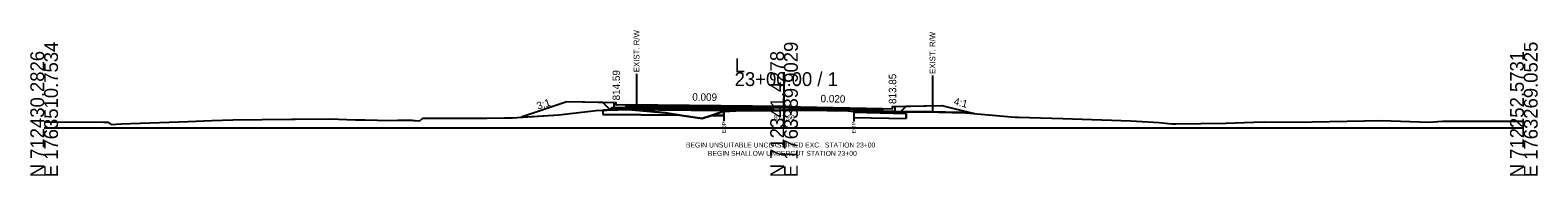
# Model space of a CAD drawing. Extents: x -26 to 5303, y -10 to 9578.
# Drawn here: x 997.2 to 1302.8, y 2990.3 to 3019.8 of the extents above; entities that cross this region are included whole.
import ezdxf

# ---------------------------------------------------------------- set-up
doc = ezdxf.new("R2010")
doc.units = 0
for name, color, linetype in [('Default', 7, 'Continuous'), ('Exist CMT Pavement', 7, 'Continuous'), ('Exist Cross Section Cell', 7, 'Continuous'), ('Exist XS Ground Line', 7, 'Continuous'), ('Old_Level_10', 7, 'Continuous'), ('Old_Level_3', 7, 'Continuous'), ('Old_Level_4', 7, 'Continuous'), ('Prop CMT Conc Surface', 7, 'Continuous'), ('Prop CMT Concrete Structures', 7, 'Continuous'), ('Prop CMT Pvmt Course 1', 7, 'Continuous'), ('Prop CMT Pvmt Course 1 CG', 7, 'Continuous'), ('Prop CMT Pvmt Course 2', 7, 'Continuous'), ('Prop CMT Pvmt Course 3', 7, 'Continuous'), ('Prop CMT Pvmt Surface', 7, 'Continuous'), ('Prop CMT Slope Grass', 7, 'Continuous'), ('Prop CMT Subgrade Earthwork', 7, 'Continuous'), ('Prop Shade Light', 7, 'Continuous'), ('Prop XS Earthwork Shape', 7, 'Continuous'), ('Prop XS Hydro Elevations', 7, 'Continuous'), ('Prop XS SE Text', 7, 'Continuous'), ('Prop XS Side Slope Text', 7, 'Continuous'), ('Prop XS Wedging', 7, 'Continuous'), ('Scratch_Level_5', 7, 'Continuous')]:
    doc.layers.add(name, color=color, linetype=linetype)

msp = doc.modelspace()

# ---------------------------------------------------------------- linework, layer by layer
at = {"layer": 'Exist CMT Pavement'}
msp.add_lwpolyline([(1137.83, 3003.42), (1137.83, 3003.42), (1138.42, 3003.4), (1139.02, 3003.42), (1140.22, 3003.47), (1142.12, 3003.51), (1142.85, 3003.52), (1145.22, 3003.53), (1146.08, 3003.54), (1147.38, 3003.56), (1148.33, 3003.57), (1149.16, 3003.57), (1150.15, 3003.67), (1150.94, 3003.59), (1151.43, 3003.58), (1152.74, 3003.59), (1154.53, 3003.59), (1156.32, 3003.58), (1157.64, 3003.58), (1158.1, 3003.58), (1158.74, 3003.57), (1159.89, 3003.56), (1160.74, 3003.55), (1161.68, 3003.53), (1162.96, 3003.46), (1163.64, 3003.42), (1164.14, 3003.37)], dxfattribs=at)
at = {"layer": 'Exist Cross Section Cell'}
for p, q in [((1150, 3000), (1150, 3011.3)), ((1000, 3000), (1150, 3000)), ((1150, 3000), (1300, 3000))]:
    msp.add_line(p, q, dxfattribs=at)
at = {"layer": 'Exist XS Ground Line'}
msp.add_lwpolyline([(1000, 3001.27), (1012.09, 3001.21), (1012.9, 3001.2), (1013.58, 3000.72), (1015.59, 3000.85), (1029.19, 3001.3), (1034, 3001.53), (1038.28, 3001.63), (1050.16, 3001.77), (1050.88, 3001.77), (1057.92, 3001.82), (1063.1, 3001.68), (1065.08, 3001.67), (1070.1, 3001.54), (1071.71, 3001.55), (1074.52, 3001.56), (1074.9, 3001.54), (1075.22, 3001.52), (1076.19, 3001.48), (1076.78, 3001.98), (1077.17, 3001.98), (1078.35, 3001.98), (1089.8, 3001.98), (1093.3, 3002.03), (1094.92, 3002.08), (1104.38, 3002.65), (1111.92, 3003.55), (1118.41, 3003.77), (1125.95, 3003.04), (1129.72, 3002.46), (1133.44, 3001.95), (1135.28, 3002.52), (1137.83, 3003.42), (1138.42, 3003.4), (1139.02, 3003.42), (1140.22, 3003.47), (1142.12, 3003.51), (1143.8, 3003.53), (1145.22, 3003.53), (1145.59, 3003.53), (1146.08, 3003.54), (1147.38, 3003.56), (1148.33, 3003.57), (1149.41, 3003.61), (1150.15, 3003.67), (1150.94, 3003.59), (1151.43, 3003.58), (1152.74, 3003.59), (1154.57, 3003.59), (1157.64, 3003.58), (1158.1, 3003.58), (1158.74, 3003.57), (1159.89, 3003.56), (1160.74, 3003.55), (1161.68, 3003.53), (1162.96, 3003.46), (1163.64, 3003.42), (1164.14, 3003.37), (1164.9, 3003.35), (1165.26, 3003.34), (1167.18, 3003.34), (1168.83, 3003.34), (1170.05, 3003.31), (1170.62, 3003.3), (1171.4, 3003.29), (1172.41, 3003.29), (1173.15, 3003.29), (1174.2, 3003.28), (1175.62, 3003.28), (1176.26, 3003.28), (1177.78, 3003.28), (1179.36, 3003.26), (1179.84, 3003.25), (1181.35, 3003.22), (1182.46, 3003.2), (1182.77, 3003.19), (1184.06, 3003.16), (1184.93, 3003.13), (1185.55, 3003.12), (1186.12, 3003.11), (1195.32, 3002.31), (1196.77, 3002.17), (1197.51, 3002.18), (1206.51, 3001.89), (1220.3, 3001.48), (1226.08, 3001.1), (1228.6, 3000.85), (1229.42, 3000.86), (1239.56, 3000.97), (1245.23, 3001.19), (1247.41, 3001.22), (1255.73, 3001.21), (1257.07, 3001.23), (1271.18, 3001.51), (1280.74, 3001.19), (1283.49, 3001.37), (1299.54, 3001.36), (1300, 3001.36)], dxfattribs=at)
at = {"layer": 'Old_Level_10'}
for p, q in [((1120.1, 3011), (1120.1, 3003.6)), ((1180.1, 3010.65), (1180.1, 3003.25)), ((1137.83, 3003.42), (1137.83, 3001.36)), ((1164.14, 3003.37), (1164.14, 3001.32))]:
    msp.add_line(p, q, dxfattribs=at)
at = {"layer": 'Prop CMT Conc Surface'}
for points in [[(1116, 3004.59), (1116, 3005.09), (1115.5, 3005.09)], [(1118, 3004.66), (1116, 3004.59)], [(1170, 3003.97), (1172, 3003.85)], [(1172, 3003.85), (1172, 3004.35), (1172.5, 3004.35)]]:
    msp.add_lwpolyline(points, dxfattribs=at)
at = {"layer": 'Prop CMT Concrete Structures'}
for points in [[(1118, 3004.66), (1116, 3004.59), (1116, 3005.09), (1115.5, 3005.09)], [(1115.5, 3005.09), (1115.5, 3004.09), (1118, 3004.07)], [(1118, 3004.07), (1118, 3004.66)], [(1170, 3003.97), (1172, 3003.85), (1172, 3004.35), (1172.5, 3004.35)], [(1172.5, 3004.35), (1172.5, 3003.34), (1170, 3003.39)], [(1170, 3003.39), (1170, 3003.97)]]:
    msp.add_lwpolyline(points, dxfattribs=at)
at = {"layer": 'Prop CMT Pvmt Course 1'}
for points in [[(1150, 3004.37), (1118, 3004.66)], [(1118, 3004.66), (1118, 3004.41)], [(1118, 3004.41), (1137.83, 3004.23)], [(1137.83, 3004.23), (1137.83, 3004.23)], [(1137.83, 3004.23), (1150, 3004.12)], [(1150, 3004.12), (1150, 3004.37)], [(1150, 3004.37), (1170, 3003.97)], [(1150, 3004.12), (1150, 3004.12), (1150, 3004.12)], [(1164.14, 3003.84), (1150, 3004.12)], [(1170, 3003.72), (1164.14, 3003.84)], [(1164.14, 3003.84), (1164.14, 3003.84)], [(1170, 3003.97), (1170, 3003.72)]]:
    msp.add_lwpolyline(points, dxfattribs=at)
at = {"layer": 'Prop CMT Pvmt Course 1 CG'}
for points in [[(1118, 3004.07), (1115, 3004.1), (1114.67, 3003.77)], [(1114.67, 3003.77), (1118, 3003.74)], [(1118, 3003.74), (1118, 3004.07)], [(1170, 3003.39), (1173, 3003.33), (1173.34, 3002.99)], [(1170, 3003.06), (1170, 3003.39)], [(1173.34, 3002.99), (1170, 3003.06)]]:
    msp.add_lwpolyline(points, dxfattribs=at)
at = {"layer": 'Prop CMT Pvmt Course 2'}
for points in [[(1137.83, 3004.23), (1118, 3004.41)], [(1118, 3004.41), (1118, 3004.07)], [(1118, 3004.07), (1137.83, 3003.9)], [(1137.83, 3003.9), (1137.83, 3004.23)], [(1164.14, 3003.51), (1164.14, 3003.84)], [(1164.14, 3003.84), (1170, 3003.72)], [(1170, 3003.39), (1164.14, 3003.51)], [(1170, 3003.72), (1170, 3003.39)]]:
    msp.add_lwpolyline(points, dxfattribs=at)
at = {"layer": 'Prop CMT Pvmt Course 3'}
for points in [[(1137.83, 3003.9), (1118, 3004.07)], [(1118, 3004.07), (1118, 3003.74)], [(1118, 3003.74), (1137.83, 3003.56)], [(1137.83, 3003.56), (1137.83, 3003.9)], [(1164.14, 3003.51), (1170, 3003.39)], [(1164.14, 3003.17), (1164.14, 3003.51)], [(1170, 3003.06), (1164.14, 3003.17)], [(1170, 3003.39), (1170, 3003.06)]]:
    msp.add_lwpolyline(points, dxfattribs=at)
at = {"layer": 'Prop CMT Pvmt Surface'}
for points in [[(1150, 3004.37), (1118, 3004.66)], [(1150, 3004.37), (1170, 3003.97)]]:
    msp.add_lwpolyline(points, dxfattribs=at)
at = {"layer": 'Prop CMT Slope Grass'}
msp.add_line((1106, 3005.28), (1096.72, 3002.19), dxfattribs=at)
for points in [[(1115.5, 3005.09), (1106, 3005.28)], [(1172.5, 3004.35), (1182, 3004.54), (1188.56, 3002.9)]]:
    msp.add_lwpolyline(points, dxfattribs=at)
at = {"layer": 'Prop CMT Subgrade Earthwork'}
for p, q in [((1137.83, 3003.56), (1137.83, 3003.42)), ((1164.14, 3003.37), (1164.14, 3003.17))]:
    msp.add_line(p, q, dxfattribs=at)
for points in [[(1118, 3003.74), (1114.67, 3003.77), (1113.3, 3005.14)], [(1137.83, 3003.56), (1118, 3003.74)], [(1164.14, 3003.17), (1170, 3003.06)], [(1170, 3003.06), (1173.34, 3002.99), (1174.75, 3004.4)]]:
    msp.add_lwpolyline(points, dxfattribs=at)
at = {"layer": 'Prop Shade Light'}
for p, q in [((1117.68, 3003.74), (1113.3, 3003.59)), ((1113.3, 3003.59), (1113.3, 3002.74)), ((1113.3, 3003.59), (1113.3, 3002.74)), ((1113.3, 3002.74), (1128.77, 3002.61)), ((1118, 3003.74), (1117.68, 3003.74)), ((1118.77, 3003.73), (1118, 3003.74)), ((1137.83, 3003.42), (1135.37, 3002.55)), ((1135.37, 3002.55), (1137.83, 3002.53)), ((1137.83, 3003.56), (1137.83, 3002.53)), ((1137.83, 3002.53), (1137.83, 3003.42)), ((1164.14, 3003.17), (1164.14, 3002.13)), ((1170, 3003.06), (1164.14, 3003.17)), ((1164.14, 3003.17), (1164.14, 3002.13)), ((1164.14, 3002.13), (1174.75, 3001.92)), ((1173.34, 3002.99), (1170, 3003.06)), ((1174.75, 3002.96), (1173.34, 3002.99)), ((1173.34, 3002.99), (1173.34, 3002.99)), ((1174.75, 3002.96), (1174.75, 3001.92)), ((1174.75, 3001.92), (1174.75, 3002.96))]:
    msp.add_line(p, q, dxfattribs=at)
for points in [[(1128.77, 3002.61), (1113.3, 3002.74)], [(1128.77, 3002.61), (1125.95, 3003.04), (1120.1, 3003.6), (1118.77, 3003.73)], [(1137.83, 3002.53), (1135.38, 3002.55)], [(1164.14, 3003.17), (1174.75, 3002.96)], [(1164.14, 3002.13), (1174.75, 3001.92)]]:
    msp.add_lwpolyline(points, dxfattribs=at)
at = {"layer": 'Prop XS Earthwork Shape'}
for points in [[(1104.38, 3002.65), (1111.92, 3003.55), (1117.68, 3003.74), (1114.67, 3003.77), (1113.3, 3005.14), (1106, 3005.28), (1096.72, 3002.19)], [(1117.68, 3003.74), (1118.41, 3003.77), (1118.77, 3003.73), (1118, 3003.74)], [(1137.83, 3003.56), (1137.83, 3003.42), (1135.28, 3002.52), (1133.44, 3001.95), (1129.72, 3002.46), (1125.95, 3003.04), (1118.77, 3003.73)], [(1173.34, 3002.99), (1173.64, 3003.29), (1173.15, 3003.29), (1172.41, 3003.29), (1171.4, 3003.29), (1170.62, 3003.3), (1170.05, 3003.31), (1168.83, 3003.34), (1167.18, 3003.34), (1165.26, 3003.34), (1164.9, 3003.35), (1164.14, 3003.37), (1164.14, 3003.17), (1170, 3003.06)], [(1182, 3004.54), (1188.56, 3002.9), (1186.12, 3003.11), (1185.55, 3003.12), (1184.93, 3003.13), (1184.06, 3003.16), (1182.77, 3003.19), (1182.46, 3003.2), (1179.84, 3003.25), (1179.36, 3003.26), (1177.78, 3003.28), (1176.26, 3003.28), (1175.62, 3003.28), (1174.2, 3003.28), (1173.64, 3003.29), (1174.75, 3004.4)]]:
    msp.add_lwpolyline(points, close=True, dxfattribs=at)
at = {"layer": 'Prop XS Wedging'}
for points in [[(1137.83, 3003.41), (1137.83, 3004.23), (1138.42, 3004.22), (1139.02, 3004.22), (1140.22, 3004.21), (1142.12, 3004.19), (1142.85, 3004.19), (1145.22, 3004.16), (1146.08, 3004.16), (1147.37, 3004.15), (1148.33, 3004.14), (1149.16, 3004.13), (1150, 3004.12), (1150.15, 3004.12), (1150.94, 3004.1), (1151.43, 3004.09), (1152.74, 3004.07), (1154.53, 3004.03), (1156.32, 3004), (1157.64, 3003.97), (1158.1, 3003.96), (1158.74, 3003.95), (1159.89, 3003.92), (1160.74, 3003.91), (1161.68, 3003.89), (1162.96, 3003.86), (1163.64, 3003.85), (1164.14, 3003.84), (1164.14, 3003.37), (1163.64, 3003.42), (1162.96, 3003.46), (1161.68, 3003.53), (1160.74, 3003.55), (1159.89, 3003.55), (1158.74, 3003.57), (1158.1, 3003.58), (1157.64, 3003.58), (1156.32, 3003.58), (1154.53, 3003.59), (1152.74, 3003.59), (1151.43, 3003.58), (1150.94, 3003.59), (1150.15, 3003.67), (1150, 3003.66), (1149.16, 3003.57), (1148.33, 3003.57), (1147.37, 3003.56), (1146.08, 3003.54), (1145.22, 3003.53), (1142.85, 3003.52), (1142.12, 3003.51), (1140.22, 3003.47), (1139.02, 3003.42), (1138.42, 3003.4)], [(1137.83, 3003.41), (1137.83, 3003.9), (1138.42, 3003.89), (1139.02, 3003.89), (1140.22, 3003.88), (1142.12, 3003.86), (1142.85, 3003.86), (1145.22, 3003.83), (1146.08, 3003.83), (1147.37, 3003.82), (1147.83, 3003.81), (1148.07, 3003.56), (1147.37, 3003.56), (1146.08, 3003.54), (1145.22, 3003.53), (1142.85, 3003.52), (1142.12, 3003.51), (1140.22, 3003.47), (1139.02, 3003.42), (1138.42, 3003.4)]]:
    msp.add_lwpolyline(points, close=True, dxfattribs=at)
at = {"layer": 'Scratch_Level_5'}
msp.add_line((1118.36, 3003.74), (1118.39, 3003.77), dxfattribs=at)

# ---------------------------------------------------------------- texts
at = {"layer": 'Default'}
msp.add_text('-', height=0.0001, dxfattribs=at).set_placement((1000, 3000))
at = {"layer": 'Exist Cross Section Cell'}
for s, p in [('E 1763510.7534', (1002.8, 2990)), ('E 1763389.9029', (1152.8, 2990)), ('E 1763269.0525', (1302.8, 2990)), ('N 712430.2826', (1000, 2990)), ('N 712341.4278', (1150, 2990)), ('N 712252.5731', (1300, 2990))]:
    msp.add_text(s, height=2.8, rotation=90, dxfattribs=at).set_placement(p)
for s, p in [('L', (1140, 3011.3)), ('23+00.00 / 1', (1140, 3008.5))]:
    msp.add_text(s, height=2.8, dxfattribs=at).set_placement(p)
at = {"layer": 'Old_Level_10'}
for s, height, p in [('EXIST. R/W', 1.181, (1120.69, 3011.31)), ('EXIST. R/W', 1.181, (1180.69, 3010.95)), ('EOP', 0.787, (1138.22, 2998.97)), ('EOP', 0.787, (1164.54, 2998.92))]:
    msp.add_text(s, height=height, rotation=90, dxfattribs=at).set_placement(p)
at = {"layer": 'Old_Level_3'}
msp.add_text('813.66', height=1, dxfattribs=at).set_placement((1147.95, 3001.66))
at = {"layer": 'Old_Level_4'}
msp.add_text('BEGIN SHALLOW UNDERCUT STATION 23+00', height=1, dxfattribs=at).set_placement((1134.57, 2994.36))
at = {"layer": 'Prop XS Hydro Elevations'}
for s, p in [('814.59', (1116.75, 3005.59)), ('813.85', (1172.75, 3004.85))]:
    msp.add_text(s, height=1.5, rotation=90, dxfattribs=at).set_placement(p)
at = {"layer": 'Prop XS SE Text'}
for s, rotation, p in [('0.009', 359.4925, (1131.4, 3005.54)), ('0.020', 358.8542, (1157.4, 3005.22))]:
    msp.add_text(s, height=1.5, rotation=rotation, dxfattribs=at).set_placement(p)
at = {"layer": 'Prop XS Side Slope Text'}
for s, rotation, p in [('3:1', 18.4075, (1100.15, 3003.69)), ('4:1', 345.9638, (1184.31, 3004.74))]:
    msp.add_text(s, height=1.5, rotation=rotation, dxfattribs=at).set_placement(p)
at = {"layer": 'Scratch_Level_5'}
msp.add_text('BEGIN UNSUITABLE UNCLASSIFIED EXC.  STATION 23+00', height=1, dxfattribs=at).set_placement((1130.12, 2996.05))

doc.saveas('drawing.dxf')
